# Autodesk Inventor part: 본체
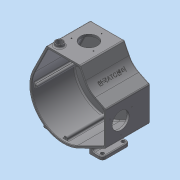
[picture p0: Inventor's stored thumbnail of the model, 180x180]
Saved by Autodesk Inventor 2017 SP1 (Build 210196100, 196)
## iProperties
Created: 2017-05
Part Number: 본체
Material: 알루미늄 6061
Document SubType Name: Modeling
Designer: mduedu
Density: 2.71 g/cm^3
Appearance: 기본값
Mass: 1345.72 g
Surface Area: 1824.08 cm^2
Volume: 496.576 cm^3
Author: mduedu
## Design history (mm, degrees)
sketch "스케치1"
  geometry: L1 (-71.801, 35.28)-(-40, 100); L2 (-40, 100)-(40, 100); L3 (40, 100)-(59.768, 59.768); L4 (59.768, 59.768)-(100, 40); L5 (100, 40)-(100, -40); L6 (100, -40)-(35.28, -71.801); A1 r 80 centre (0, 0) between (-71.801, 35.28) and (35.28, -71.801); 3 further points
  constraints: 12 end point, 4 tangent, 2 midpoint, 2 point on circle, 1 centre point, 1 coincident, 1 horizontal, 1 horizontal alignment, 1 perpendicular, 1 vertical alignment
  dimensions: "d0" = 160 diameter of A1; "d2" = 100 distance from line of L2 point (0, 0); "d3" = 100 distance from line of L5 point (0, 0); "d4" = 80 distance of L1.end L2.end; "d5" = 80 distance of L4.end L5.end
extrude "돌출1" new body sketch "스케치1" distance "d6" = 5; taper "d7" = 0 deg
fillet "모깎기1" dims "d8" = 50
sketch "스케치2"
  geometry: C1 r 22 at (0, 0); 1 further point
  constraints: 1 centre point, 1 coincident
  dimensions: "d9" = 44 diameter of C1
extrude "돌출2" join sketch "스케치2" distance "d10" = 22.5; taper "d11" = 0 deg
sketch "스케치3"
  geometry: C1 r 18.5 at (0, 0); 1 further point
  constraints: 1 centre point, 1 coincident
  dimensions: "d12" = 37 diameter of C1
extrude "돌출3" cut sketch "스케치3" distance "d13" = 9; taper "d14" = 0 deg
fillet "모깎기2" dims "d15" = 3
sketch "스케치4"
  geometry: L1 (35.28, -71.801)-(100, -40) reference; L2 (100, -40)-(100, 40) reference; L3 (100, 40)-(75.073, 52.248) reference; L4 (52.248, 75.073)-(40, 100) reference; L5 (40, 100)-(-40, 100) reference; L6 (-40, 100)-(-71.801, 35.28) reference; L7 (-36.886, 95)-(36.886, 95); L8 (36.886, 95)-(47.76, 72.868); L9 (72.868, 47.76)-(95, 36.886); L10 (95, 36.886)-(95, -36.886); L11 (95, -36.886)-(33.075, -67.313); L12 (-67.313, 33.075)-(-36.886, 95); C1 r 25 at (0, 0) reference; A1 r 50 centre (97.123, 97.123) between (52.248, 75.073) and (75.073, 52.248) reference; A2 r 80 centre (0, 0) between (-71.801, 35.28) and (35.28, -71.801) reference; A3 r 55 centre (97.123, 97.123) between (47.76, 72.868) and (72.868, 47.76); A4 r 75 centre (0, 0) between (-67.313, 33.075) and (33.075, -67.313); 1 further point
  constraints: 12 end point, 4 point on circle, 2 centre point, 7 other
  dimensions: "d16" = 5 distance between parallel lines of L7 L5
extrude "돌출4" join sketch "스케치4" distance "d17" = 100; taper "d18" = 0 deg
sketch "스케치5"
  geometry: L1 (80, 0)-(0, 0) reference; C1 r 20 at (40, -45); 2 further points
  constraints: 1 centre point, 1 midpoint, 1 vertical alignment
  dimensions: "d19" = 40 diameter of C1; "d21" = 45 distance from line of C1.centre L1
extrude "돌출5" cut sketch "스케치5" stored distance "d22" = 100; taper "d23" = 0 deg
sketch "스케치6"
  geometry: L1 (0, 0)-(0, -105) reference; L2 (80, -105)-(0, -105) reference; C1 r 9 at (14, -89); 1 further point
  constraints: 1 centre point
  dimensions: "d24" = 18 diameter of C1; "d26" = 14 distance from line of C1.centre L1; "d27" = 16 distance from line of C1.centre L2
extrude "돌출6" join sketch "스케치6" distance "d28" = 7; taper "d29" = 0 deg
hole "구멍1" diameter "d32" = 14; stored, may be unused: countersink angle "d36" = 90 deg, drill point angle "d38" = 118 deg; dims "d33" = 6, "d34" = 4, "d35" = 2, "d37" = 8, "d39" = 10, "d40" = 10
sketch "스케치7"
  geometry: L1 (-105, 0)-(-105, 80) reference; L2 (0, 0)-(0, 80) reference; C1 r 20 at (-70, 40); 2 further points
  constraints: 1 centre point, 1 horizontal alignment, 1 midpoint
  dimensions: "d41" = 40 diameter of C1; "d42" = 35 distance from line of C1.centre L1
extrude "돌출7" cut sketch "스케치7" stored distance "d43" = 7; taper "d44" = 0 deg
node "작업 평면1"
sketch "스케치8"
  geometry: L1 (47.76, 72.868)-(36.886, 95) reference; L2 (36.886, 95)-(-36.886, 95) reference; L3 (-36.886, 95)-(-67.313, 33.075) reference; L4 (33.075, -67.313)-(95, -36.886) reference; L5 (95, -36.886)-(95, 36.886) reference; L6 (95, 36.886)-(72.868, 47.76) reference; L7 (95, 36.886)-(95, -36.886) reference; L8 (-36.886, 95)-(36.886, 95) reference; L9 (36.886, 95)-(47.76, 72.868) reference; L10 (-71, 4)-(-74.893, 4); L11 (-71, -4)-(-74.893, -4); L12 (-4, -71)-(-4, -74.893); L13 (4, -71)-(4, -74.893); L14 (30.394, 91)-(30.394, 95); L15 (34.394, 87)-(40.817, 87); L16 (30.394, 95)-(36.886, 95); L17 (36.886, 95)-(37.984, 92.764); L18 (91, 30.394)-(95, 30.394); L19 (87, 34.394)-(87, 40.817); L20 (87, 40.817)-(95, 36.886); L21 (95, 36.886)-(95, 30.394); C1 r 25 at (0, 0) reference; A1 r 75 centre (0, 0) between (-67.313, 33.075) and (33.075, -67.313) reference; A2 r 55 centre (97.123, 97.123) between (47.76, 72.868) and (72.868, 47.76) reference; A3 r 4 centre (-71, 0) between (-71, 4) and (-71, -4); A4 r 4 centre (0, -71) between (-4, -71) and (4, -71); A5 r 4 centre (34.394, 91) between (30.394, 91) and (34.394, 87); A6 r 75 centre (0, 0) between (-67.313, 33.075) and (33.075, -67.313) reference; A7 r 4 centre (91, 34.394) between (91, 30.394) and (87, 34.394); 1 further point
  constraints: 24 end point, 17 point on circle, 14 tangent, 5 point on line, 4 centre point, 3 equal radius, 3 perpendicular, 3 vertical, 2 collinear, 2 horizontal, 1 horizontal alignment, 1 parallel, 1 vertical alignment
  dimensions: "d46" = 8 diameter of A3
extrude "돌출8" join sketch "스케치8" stored distance "d49" = 7; taper "d50" = 0 deg
node "작업 평면2"
sketch "스케치9"
  geometry: L1 (71.801, 0)-(71.801, 105) reference; L2 (71.801, 0)-(-35.28, 0) reference; L3 (-35.28, 0)-(-35.28, 105) reference; L4 (71.801, 105)-(-35.28, 105) reference; L5 (40, 0)-(40, 105) reference; L6 (71.801, 52.5)-(-35.28, 52.5); L7 (71.801, 20)-(40, 20); L8 (40, 20)-(40, 85); L9 (40, 85)-(71.801, 85); L10 (71.801, 85)-(71.801, 20); 1 further point
  constraints: 10 end point, 2 midpoint, 2 parallel, 2 point on line, 1 horizontal, 1 perpendicular, 1 other
  dimensions: "d52" = 20 distance between parallel lines of L7 L2
extrude "돌출9" join sketch "스케치9" distance "d53" = 8; taper "d54" = 0 deg
fillet "모깎기3" dims "d55" = 8
sketch "스케치10"
  geometry: C1 r 4 at (-63.801, -28); C2 r 4 at (-63.801, -77); A1 r 8 centre (-63.801, -28) between (-63.801, -20) and (-71.801, -28) reference; A2 r 8 centre (-63.801, -77) between (-71.801, -77) and (-63.801, -85) reference; 1 further point
  constraints: 2 centre point, 2 coincident, 1 equal radius
  dimensions: "d56" = 8 diameter of C1
extrude "돌출10" cut sketch "스케치10" stored distance "d57" = 50.5; taper "d58" = 0 deg
sketch "스케치11"
  geometry: L1 (-63.801, -20)-(-40, -20) reference; L2 (-40, -20)-(-40, -85) reference; L3 (-40, -85)-(-63.801, -85) reference; L4 (-71.801, -77)-(-71.801, -28) reference; L5 (71.801, -77)-(71.801, -28) reference; L6 (40, -85)-(63.801, -85) reference; L7 (40, -20)-(40, -85) reference; L8 (63.801, -20)-(40, -20) reference; L9 (-40, -85)-(-48, -85); L10 (-48, -85)-(-48, -20); L11 (-48, -20)-(-40, -20); L12 (-40, -20)-(-40, -85); L13 (40, -85)-(48, -85); L14 (48, -85)-(48, -20); L15 (48, -20)-(40, -20); L16 (40, -20)-(40, -85); C1 r 4 at (-63.801, -28) reference; C2 r 4 at (-63.801, -77) reference; C3 r 4 at (63.801, -28) reference; C4 r 4 at (63.801, -77) reference; A1 r 8 centre (-63.801, -28) between (-63.801, -20) and (-71.801, -28) reference; A2 r 8 centre (-63.801, -77) between (-71.801, -77) and (-63.801, -85) reference; A3 r 8 centre (63.801, -28) between (71.801, -28) and (63.801, -20) reference; A4 r 8 centre (63.801, -77) between (63.801, -85) and (71.801, -77) reference; 1 further point
  constraints: 16 end point, 4 parallel, 2 horizontal, 2 perpendicular, 2 point on line
  dimensions: "d59" = 8 distance of L10.end L11.end; "d61" = 8 distance of L14.end L15.end
extrude "돌출11" join sketch "스케치11" stored distance "d62" = 5; taper "d63" = 0 deg
fillet "모깎기4" dims "d64" = 5
fillet "모깎기5" dims "d65" = 2
fillet "모깎기6" dims "d66" = 2
fillet "모깎기8" dims "d68" = 2
fillet "모깎기9" dims "d70" = 3, "d101" = 1
fillet "모깎기10" dims "d71" = 3
fillet "모깎기11" dims "d72" = 3
fillet "모깎기12" dims "d73" = 3
fillet "모깎기13" dims "d76" = 3
chamfer "모따기1" distance "d77" = 0.5; stored, may be unused: second distance "d78" = 2, angle "d79" = 45 deg
chamfer "모따기2" distance "d87" = 1; stored, may be unused: second distance "d88" = 2, angle "d89" = 45 deg
chamfer "모따기3" distance "d90" = 1; stored, may be unused: second distance "d91" = 2, angle "d92" = 45 deg
sketch "스케치14"
  geometry: 3 further points
  constraints: 3 other
hole "구멍2" sketch "스케치14" at (-55.375, -40), (-3.414, -40), (-29.394, -85) diameter "d93" = 2.459; stored, may be unused: countersink angle "d97" = 90 deg, drill point angle "d99" = 0 deg; dims "d94" = 6, "d95" = 4, "d96" = 2, "d98" = 8
sketch "스케치15"
  geometry: 3 further points
  constraints: 3 other
hole "구멍4" sketch "스케치15" at (-55.981, -14.394), (-4.019, -14.394), (-30, -59.394) diameter "d102" = 2.459; stored, may be unused: countersink angle "d106" = 90 deg, drill point angle "d108" = 0 deg; dims "d103" = 6, "d104" = 4, "d105" = 2, "d107" = 8
sketch "스케치16"
  geometry: 4 further points
  constraints: 4 other
hole "구멍6" sketch "스케치16" at (0, -71), (91, 34.394), (34.394, 91), (-71, 0) diameter "d109" = 2.459; stored, may be unused: countersink angle "d113" = 90 deg, drill point angle "d115" = 120 deg; dims "d110" = 8.5, "d111" = 4, "d112" = 2, "d114" = 10
node "작업 평면4"
sketch "스케치17"
  geometry: 2 further points
  constraints: 1 horizontal alignment, 1 other
  dimensions: "d116" = 52.5 distance of point (0, 16.14) point (52.5, 16.14)
feature "엠보싱2" sketch "스케치17" dims "d117" = 0.5, "d118" = 0
node "솔리드1"
mirror "대칭1"
node "투영된 루프1"
node "투영된 루프2"
node "투영된 루프3"
node "투영된 루프4"
node "투영된 루프5"
other parameters: "d45" = 95
